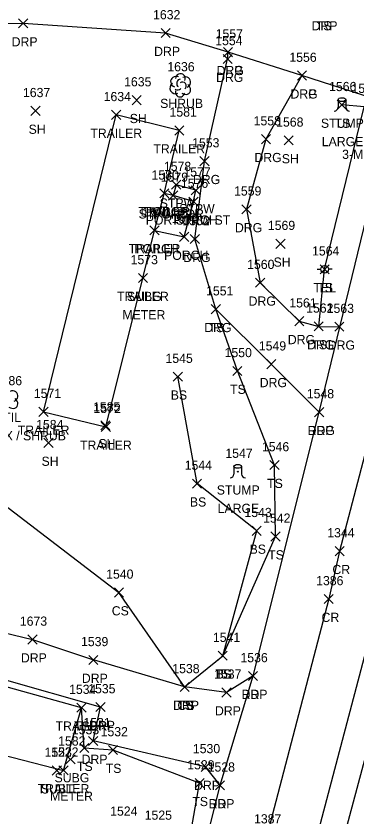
# Model space of a CAD drawing. Extents: x 1477930 to 1480780, y 774090 to 784647.
# Drawn here: x 1479279.7 to 1479353.8, y 774335.2 to 774509.5 of the extents above; entities that cross this region are included whole.
import ezdxf

# ---------------------------------------------------------------- set-up
doc = ezdxf.new("R2010")
doc.units = 0
for name, color, linetype in [('L_A', 7, 'Continuous'), ('L_C', 7, 'Continuous'), ('L_I', 7, 'Continuous'), ('L_TIC', 7, 'Continuous'), ('LBC', 7, 'Continuous'), ('LBF', 7, 'Continuous'), ('LELB', 7, 'Continuous'), ('LSH', 7, 'Continuous'), ('LTD', 7, 'Continuous'), ('LTS', 7, 'Continuous'), ('P_A', 7, 'Continuous'), ('P_I', 7, 'Continuous'), ('P_TIC', 7, 'Continuous'), ('PET', 7, 'Continuous'), ('PRC', 7, 'Continuous'), ('R_A', 7, 'Continuous'), ('R_I', 7, 'Continuous'), ('R_TIC', 7, 'Continuous'), ('RDG', 7, 'Continuous'), ('RDP', 7, 'Continuous'), ('RSW', 7, 'Continuous'), ('U_A', 7, 'Continuous'), ('U_C', 7, 'Continuous'), ('U_I', 7, 'Continuous'), ('U_TIC', 7, 'Continuous'), ('UP', 7, 'Continuous')]:
    doc.layers.add(name, color=color, linetype=linetype)

msp = doc.modelspace()

# ---------------------------------------------------------------- linework, layer by layer
at = {"layer": 'L_TIC'}
for points in [[(1479304.99, 774490.19), (1479306.99, 774492.19)], [(1479306.99, 774490.19), (1479304.99, 774492.19)], [(1479282.93, 774487.85), (1479284.93, 774489.85)], [(1479284.93, 774487.85), (1479282.93, 774489.85)], [(1479349.75, 774489.16), (1479351.75, 774491.16)], [(1479351.75, 774489.16), (1479349.75, 774491.16)], [(1479300.53, 774486.97), (1479302.53, 774488.97)], [(1479302.53, 774486.97), (1479300.53, 774488.97)], [(1479300.53, 774486.97), (1479302.53, 774488.97)], [(1479302.53, 774486.97), (1479300.53, 774488.97)], [(1479314.29, 774483.59), (1479316.29, 774485.59)], [(1479316.29, 774483.59), (1479314.29, 774485.59)], [(1479338.16, 774481.42), (1479340.16, 774483.42)], [(1479340.16, 774481.42), (1479338.16, 774483.42)], [(1479313.62, 774471.76), (1479315.62, 774473.76)], [(1479315.62, 774471.76), (1479313.62, 774473.76)], [(1479317.89, 774470.55), (1479319.89, 774472.55)], [(1479319.89, 774470.55), (1479317.89, 774472.55)], [(1479311.01, 774469.88), (1479313.01, 774471.88)], [(1479313.01, 774469.88), (1479311.01, 774471.88)], [(1479311.01, 774469.88), (1479313.01, 774471.88)], [(1479313.01, 774469.88), (1479311.01, 774471.88)], [(1479312.95, 774469.4), (1479314.95, 774471.4)], [(1479314.95, 774469.4), (1479312.95, 774471.4)], [(1479312.95, 774469.4), (1479314.95, 774471.4)], [(1479314.95, 774469.4), (1479312.95, 774471.4)], [(1479317.39, 774468.08), (1479319.39, 774470.08)], [(1479319.39, 774468.08), (1479317.39, 774470.08)], [(1479317.39, 774468.08), (1479319.39, 774470.08)], [(1479319.39, 774468.08), (1479317.39, 774470.08)], [(1479308.89, 774461.82), (1479310.89, 774463.82)], [(1479310.89, 774461.82), (1479308.89, 774463.82)], [(1479308.89, 774461.82), (1479310.89, 774463.82)], [(1479310.89, 774461.82), (1479308.89, 774463.82)], [(1479315.34, 774460.39), (1479317.34, 774462.39)], [(1479317.34, 774460.39), (1479315.34, 774462.39)], [(1479336.36, 774458.9), (1479338.36, 774460.9)], [(1479338.36, 774458.9), (1479336.36, 774460.9)], [(1479345.99, 774453.34), (1479347.99, 774455.34)], [(1479347.99, 774453.34), (1479345.99, 774455.34)], [(1479306.36, 774451.43), (1479308.36, 774453.43)], [(1479308.36, 774451.43), (1479306.36, 774453.43)], [(1479322.25, 774444.64), (1479324.25, 774446.64)], [(1479324.25, 774444.64), (1479322.25, 774446.64)], [(1479344.69, 774440.89), (1479346.69, 774442.89)], [(1479346.69, 774440.89), (1479344.69, 774442.89)], [(1479326.95, 774431.19), (1479328.95, 774433.19)], [(1479328.95, 774431.19), (1479326.95, 774433.19)], [(1479313.97, 774429.94), (1479315.97, 774431.94)], [(1479315.97, 774429.94), (1479313.97, 774431.94)], [(1479284.68, 774422.29), (1479286.68, 774424.29)], [(1479286.68, 774422.29), (1479284.68, 774424.29)], [(1479284.68, 774422.29), (1479286.68, 774424.29)], [(1479286.68, 774422.29), (1479284.68, 774424.29)], [(1479298.17, 774419.35), (1479300.17, 774421.35)], [(1479300.17, 774419.35), (1479298.17, 774421.35)], [(1479298.27, 774419.01), (1479300.27, 774421.01)], [(1479300.27, 774419.01), (1479298.27, 774421.01)], [(1479285.75, 774415.51), (1479287.75, 774417.51)], [(1479287.75, 774415.51), (1479285.75, 774417.51)], [(1479335.05, 774410.68), (1479337.05, 774412.68)], [(1479337.05, 774410.68), (1479335.05, 774412.68)], [(1479318.16, 774406.64), (1479320.16, 774408.64)], [(1479320.16, 774406.64), (1479318.16, 774408.64)], [(1479331.18, 774396.35), (1479333.18, 774398.35)], [(1479333.18, 774396.35), (1479331.18, 774398.35)], [(1479335.27, 774395.12), (1479337.27, 774397.12)], [(1479337.27, 774395.12), (1479335.27, 774397.12)], [(1479301.12, 774382.92), (1479303.12, 774384.92)], [(1479303.12, 774382.92), (1479301.12, 774384.92)], [(1479323.75, 774369.14), (1479325.75, 774371.14)], [(1479325.75, 774369.14), (1479323.75, 774371.14)], [(1479323.75, 774369.14), (1479325.75, 774371.14)], [(1479325.75, 774369.14), (1479323.75, 774371.14)], [(1479315.45, 774362.33), (1479317.45, 774364.33)], [(1479317.45, 774362.33), (1479315.45, 774364.33)], [(1479315.45, 774362.33), (1479317.45, 774364.33)], [(1479317.45, 774362.33), (1479315.45, 774364.33)], [(1479292.95, 774357.81), (1479294.95, 774359.81)], [(1479294.95, 774357.81), (1479292.95, 774359.81)], [(1479292.95, 774357.81), (1479294.95, 774359.81)], [(1479294.95, 774357.81), (1479292.95, 774359.81)], [(1479293.56, 774349.02), (1479295.56, 774351.02)], [(1479295.56, 774349.02), (1479293.56, 774351.02)], [(1479299.83, 774348.59), (1479301.83, 774350.59)], [(1479301.83, 774348.59), (1479299.83, 774350.59)], [(1479289.03, 774344.16), (1479291.03, 774346.16)], [(1479291.03, 774344.16), (1479289.03, 774346.16)], [(1479318.72, 774341.37), (1479320.72, 774343.37)], [(1479320.72, 774341.37), (1479318.72, 774343.37)]]:
    msp.add_lwpolyline(points, dxfattribs=at)
at = {"layer": 'LBC'}
for points in [[(1479285.68, 774423.29), (1479299.27, 774420.01), (1479307.36, 774452.43), (1479309.89, 774462.82), (1479312.01, 774470.88), (1479315.29, 774484.59), (1479301.53, 774487.97)], [(1479285.68, 774423.29), (1479301.53, 774487.97)], [(1479220.31, 774364.01), (1479269.03, 774350.77), (1479272.25, 774349.73), (1479290.03, 774345.16), (1479293.95, 774358.81), (1479249.22, 774371.2), (1479239.25, 774373.93), (1479224.24, 774377.86)]]:
    msp.add_lwpolyline(points, dxfattribs=at)
at = {"layer": 'LBF'}
for points in [[(1479318.39, 774469.08), (1479318.89, 774471.55), (1479314.62, 774472.76), (1479313.95, 774470.4)], [(1479309.89, 774462.82), (1479316.34, 774461.39), (1479318.39, 774469.08), (1479313.95, 774470.4), (1479312.01, 774470.88)]]:
    msp.add_lwpolyline(points, dxfattribs=at)
at = {"layer": 'LELB'}
for points in [[(1479345.69, 774441.89), (1479346.99, 774454.34), (1479355.59, 774489.75), (1479350.75, 774490.16)], [(1479316.45, 774363.33), (1479324.75, 774370.14), (1479336.27, 774396.12), (1479336.05, 774411.68), (1479327.95, 774432.19), (1479323.25, 774445.64)], [(1479324.75, 774370.14), (1479332.18, 774397.35), (1479319.16, 774407.64), (1479314.97, 774430.94)], [(1479269.11, 774409.12), (1479302.12, 774383.92)], [(1479316.45, 774363.33), (1479302.12, 774383.92)], [(1479286.59, 774212.27), (1479303.75, 774279.72), (1479306.97, 774294.46), (1479314.06, 774320.63), (1479317.48, 774329.95), (1479319.72, 774342.37), (1479300.83, 774349.59), (1479294.56, 774350.02), (1479293.95, 774358.81)]]:
    msp.add_lwpolyline(points, dxfattribs=at)
at = {"layer": 'LSH'}
msp.add_line((1479315.48, 774494.48), (1479315.48, 774494.48), dxfattribs=at)
msp.add_line((1479315.48, 774494.48), (1479315.48, 774494.48), dxfattribs=at)
msp.add_arc((1479315.53, 774495.91), 1.05, 335.5272, 180.9563, dxfattribs=at)
for centre, major_axis, ratio, start_param, end_param in [((1479314.69, 774495.15), (1.21, -0.51), 0.895232, 1.570796, 4.712389), ((1479315.27, 774494.94), (-0.208, -0.792), 0.645439, 3.141593, 6.283185), ((1479315.98, 774494.31), (-0.5, 0.667), 0.989748, 3.141593, 6.283185), ((1479316.52, 774495.06), (-1.14, -0.48), 0.949671, 1.570796, 4.712389), ((1479314.4, 774493.77), (0.58, -1.04), 0.959034, 3.141593, 6.283185), ((1479315.48, 774492.98), (0.26, 1.06), 0.942809, 1.570796, 4.712389), ((1479315.02, 774493.73), (-0.625, -0.083), 0.423636, 0, 3.141593), ((1479316.48, 774493.65), (-1.09, 0.79), 0.841452, 1.570796, 4.712389)]:
    msp.add_ellipse(centre, major_axis=major_axis, ratio=ratio, start_param=start_param, end_param=end_param, dxfattribs=at)
at = {"layer": 'LTD'}
for centre, major_axis, ratio in [((1479278.84, 774426.65), (-1.14, -0.48), 0.949671), ((1479278.8, 774425.23), (-1.09, 0.79), 0.841452)]:
    msp.add_ellipse(centre, major_axis=major_axis, ratio=ratio, start_param=1.570796, end_param=4.712389, dxfattribs=at)
at = {"layer": 'LTS'}
for p, q in [((1479349.92, 774491.3), (1479349.92, 774489.64)), ((1479350.76, 774490.16), (1479350.76, 774490.16)), ((1479350.76, 774490.16), (1479350.76, 774490.16)), ((1479350.76, 774490.14), (1479350.76, 774490.14)), ((1479351.59, 774491.14), (1479351.59, 774491.3)), ((1479351.59, 774491.3), (1479351.59, 774489.64)), ((1479327.21, 774411.39), (1479327.21, 774409.73)), ((1479328.87, 774411.23), (1479328.87, 774411.39)), ((1479328.87, 774411.39), (1479328.87, 774409.73)), ((1479328.04, 774410.25), (1479328.04, 774410.25)), ((1479328.04, 774410.25), (1479328.04, 774410.25)), ((1479328.04, 774410.23), (1479328.04, 774410.23))]:
    msp.add_line(p, q, dxfattribs=at)
for centre in [(1479350.76, 774490.16), (1479328.04, 774410.25)]:
    msp.add_circle(centre, 0.0833, dxfattribs=at)
for centre, start, end in [((1479349.09, 774489.64), 270, 360), ((1479352.42, 774489.64), 180, 270), ((1479326.37, 774409.73), 270, 360), ((1479329.71, 774409.73), 180, 270)]:
    msp.add_arc(centre, 0.833, start, end, dxfattribs=at)
for centre in [(1479350.76, 774491.3), (1479328.04, 774411.39)]:
    msp.add_ellipse(centre, major_axis=(-0.833, 0), ratio=0.5, dxfattribs=at)
at = {"layer": 'P_TIC'}
for points in [[(1479344.79, 774422.22), (1479346.79, 774424.22)], [(1479346.79, 774422.22), (1479344.79, 774424.22)], [(1479349.26, 774391.93), (1479351.26, 774393.93)], [(1479351.26, 774391.93), (1479349.26, 774393.93)], [(1479346.88, 774381.5), (1479348.88, 774383.5)], [(1479348.88, 774381.5), (1479346.88, 774383.5)], [(1479330.38, 774364.72), (1479332.38, 774366.72)], [(1479332.38, 774364.72), (1479330.38, 774366.72)], [(1479323.18, 774340.9), (1479325.18, 774342.9)], [(1479325.18, 774340.9), (1479323.18, 774342.9)]]:
    msp.add_lwpolyline(points, dxfattribs=at)
at = {"layer": 'PET'}
for points in [[(1479290.45, 774211), (1479306.91, 774277.39), (1479311.78, 774295.77), (1479318.73, 774320.25), (1479320.95, 774328.78), (1479324.18, 774341.9), (1479331.38, 774365.72), (1479345.79, 774423.22), (1479362.09, 774490.12), (1479368.03, 774516.32), (1479374.9, 774550.83), (1479383.52, 774593.51), (1479391.98, 774640.39), (1479380.39, 774660.29), (1479367.57, 774658.29), (1479344.84, 774648.04), (1479309.03, 774631.85), (1479275.88, 774616.72), (1479247.66, 774604.4), (1479226.65, 774595.78), (1479182.4, 774576.78), (1479137.48, 774556.65)], [(1479393.7, 774517.71), (1479389.34, 774499.77), (1479385.65, 774485.2), (1479372.47, 774434.64), (1479369.27, 774419.38), (1479364.55, 774403.36), (1479358.32, 774380), (1479344.31, 774327.21), (1479344.11, 774325.21), (1479340.22, 774308.9), (1479335.03, 774292.91), (1479323.53, 774246.41), (1479312.91, 774202.88), (1479309.56, 774191.22), (1479295.39, 774137.13)]]:
    msp.add_lwpolyline(points, dxfattribs=at)
at = {"layer": 'PRC'}
msp.add_lwpolyline([(1479418.32, 774694.97), (1479413.6, 774667.54), (1479403.41, 774616.88), (1479393.18, 774569.31), (1479382.15, 774520.62), (1479370.95, 774473.44), (1479362, 774437.8), (1479350.26, 774392.93), (1479347.88, 774382.5), (1479334.29, 774330.6), (1479333.84, 774328.63), (1479325.02, 774295.54), (1479313.51, 774250.57), (1479296.99, 774187.82), (1479284.93, 774140.68)], dxfattribs=at)
at = {"layer": 'R_TIC'}
for points in [[(1479280.23, 774506.91), (1479282.23, 774508.91)], [(1479282.23, 774506.91), (1479280.23, 774508.91)], [(1479311.31, 774504.81), (1479313.31, 774506.81)], [(1479313.31, 774504.81), (1479311.31, 774506.81)], [(1479324.92, 774500.65), (1479326.92, 774502.65)], [(1479326.92, 774500.65), (1479324.92, 774502.65)], [(1479324.92, 774500.65), (1479326.92, 774502.65)], [(1479326.92, 774500.65), (1479324.92, 774502.65)], [(1479324.83, 774499.16), (1479326.83, 774501.16)], [(1479326.83, 774499.16), (1479324.83, 774501.16)], [(1479341.05, 774495.54), (1479343.05, 774497.54)], [(1479343.05, 774495.54), (1479341.05, 774497.54)], [(1479341.05, 774495.54), (1479343.05, 774497.54)], [(1479343.05, 774495.54), (1479341.05, 774497.54)], [(1479333.19, 774481.69), (1479335.19, 774483.69)], [(1479335.19, 774481.69), (1479333.19, 774483.69)], [(1479319.78, 774476.9), (1479321.78, 774478.9)], [(1479321.78, 774476.9), (1479319.78, 774478.9)], [(1479328.94, 774466.4), (1479330.94, 774468.4)], [(1479330.94, 774466.4), (1479328.94, 774468.4)], [(1479317.68, 774459.92), (1479319.68, 774461.92)], [(1479319.68, 774459.92), (1479317.68, 774461.92)], [(1479331.92, 774450.41), (1479333.92, 774452.41)], [(1479333.92, 774450.41), (1479331.92, 774452.41)], [(1479322.25, 774444.64), (1479324.25, 774446.64)], [(1479324.25, 774444.64), (1479322.25, 774446.64)], [(1479340.47, 774442.02), (1479342.47, 774444.02)], [(1479342.47, 774442.02), (1479340.47, 774444.02)], [(1479344.69, 774440.89), (1479346.69, 774442.89)], [(1479346.69, 774440.89), (1479344.69, 774442.89)], [(1479349.18, 774440.82), (1479351.18, 774442.82)], [(1479351.18, 774440.82), (1479349.18, 774442.82)], [(1479334.35, 774432.65), (1479336.35, 774434.65)], [(1479336.35, 774432.65), (1479334.35, 774434.65)], [(1479344.79, 774422.22), (1479346.79, 774424.22)], [(1479346.79, 774422.22), (1479344.79, 774424.22)], [(1479282.25, 774372.67), (1479284.25, 774374.67)], [(1479284.25, 774372.67), (1479282.25, 774374.67)], [(1479295.55, 774368.22), (1479297.55, 774370.22)], [(1479297.55, 774368.22), (1479295.55, 774370.22)], [(1479330.38, 774364.72), (1479332.38, 774366.72)], [(1479332.38, 774364.72), (1479330.38, 774366.72)], [(1479315.45, 774362.33), (1479317.45, 774364.33)], [(1479317.45, 774362.33), (1479315.45, 774364.33)], [(1479324.58, 774361.14), (1479326.58, 774363.14)], [(1479326.58, 774361.14), (1479324.58, 774363.14)], [(1479297.11, 774357.95), (1479299.11, 774359.95)], [(1479299.11, 774357.95), (1479297.11, 774359.95)], [(1479295.49, 774350.57), (1479297.49, 774352.57)], [(1479297.49, 774350.57), (1479295.49, 774352.57)], [(1479320.03, 774344.9), (1479322.03, 774346.9)], [(1479322.03, 774344.9), (1479320.03, 774346.9)], [(1479323.18, 774340.9), (1479325.18, 774342.9)], [(1479325.18, 774340.9), (1479323.18, 774342.9)]]:
    msp.add_lwpolyline(points, dxfattribs=at)
at = {"layer": 'RDG'}
for points in [[(1479345.79, 774423.22), (1479335.35, 774433.65), (1479323.25, 774445.64), (1479318.68, 774460.92), (1479320.78, 774477.9), (1479325.83, 774500.16), (1479325.92, 774501.65)], [(1479342.05, 774496.54), (1479334.19, 774482.69), (1479329.94, 774467.4), (1479332.92, 774451.41), (1479341.47, 774443.02), (1479345.69, 774441.89), (1479350.18, 774441.82)]]:
    msp.add_lwpolyline(points, dxfattribs=at)
at = {"layer": 'RDP'}
for points in [[(1479362.09, 774490.12), (1479342.05, 774496.54), (1479325.92, 774501.65), (1479312.31, 774505.81), (1479281.23, 774507.91), (1479260.19, 774507.51), (1479228.52, 774504.28), (1479173.38, 774482.97), (1479136.11, 774464.13), (1479110.89, 774453.25), (1479073.73, 774438.02), (1479028.37, 774422.34), (1479014.07, 774419.45), (1479003.41, 774415.12), (1479000.29, 774404.19), (1478987.91, 774394.73), (1478976.96, 774410.39), (1478964.4, 774425.19), (1478951.82, 774441.87), (1478940.93, 774454.02), (1478935.82, 774456.7)], [(1479256.83, 774377.19), (1479257.63, 774379.86), (1479283.25, 774373.67)], [(1479283.25, 774373.67), (1479296.55, 774369.22)], [(1479324.18, 774341.9), (1479321.03, 774345.9), (1479296.49, 774351.57), (1479298.11, 774358.95), (1479255.13, 774371.1)], [(1479331.38, 774365.72), (1479325.58, 774362.14), (1479316.45, 774363.33), (1479296.55, 774369.22)]]:
    msp.add_lwpolyline(points, dxfattribs=at)
at = {"layer": 'RSW'}
msp.add_lwpolyline([(1479439.59, 774678.84), (1479428.06, 774631.68), (1479427.69, 774629.39), (1479423.62, 774612.61), (1479412.13, 774564.62), (1479400.05, 774515.9), (1479395.35, 774496.7), (1479392.07, 774484.83), (1479378.7, 774433.47), (1479373.97, 774416.64), (1479370.99, 774405.04), (1479364.01, 774378.3), (1479349.72, 774325.26), (1479349.32, 774323.81), (1479344.48, 774305.55), (1479341.14, 774293.48), (1479328.32, 774245.21), (1479314.62, 774191.4)], dxfattribs=at)
at = {"layer": 'U_TIC'}
for points in [[(1479306.36, 774451.43), (1479308.36, 774453.43)], [(1479308.36, 774451.43), (1479306.36, 774453.43)], [(1479290.56, 774346.55), (1479292.56, 774348.55)], [(1479292.56, 774346.55), (1479290.56, 774348.55)], [(1479287.59, 774344.12), (1479289.59, 774346.12)], [(1479289.59, 774344.12), (1479287.59, 774346.12)]]:
    msp.add_lwpolyline(points, dxfattribs=at)
at = {"layer": 'UP'}
for p, q in [((1479345.34, 774454.33), (1479346.16, 774454.33)), ((1479346.99, 774454.34), (1479346.99, 774454.34)), ((1479348.66, 774454.34), (1479347.83, 774454.34)), ((1479347.83, 774454.34), (1479347.83, 774454.34)), ((1479348.66, 774454.34), (1479348.66, 774454.34))]:
    msp.add_line(p, q, dxfattribs=at)
msp.add_circle((1479346.99, 774454.34), 0.833, dxfattribs=at)

# ---------------------------------------------------------------- texts
at = {"layer": 'L_A'}
for s, p in [('TS', (1479345.07, 774506.39)), ('SHRUB', (1479311.11, 774489.48)), ('SH', (1479304.48, 774486.19)), ('STUMP', (1479346.18, 774485.16)), ('TS', (1479349.16, 774485.16)), ('SH', (1479282.42, 774483.85)), ('TRAILER', (1479295.89, 774482.97)), ('TRAILER', (1479295.89, 774482.97)), ('TRAILER', (1479309.64, 774479.59)), ('SH', (1479337.65, 774477.42)), ('STPW', (1479311.02, 774467.76)), ('TRAILER', (1479306.36, 774465.88)), ('STPW POR', (1479306.4, 774465.4)), ('PORCH', (1479307.63, 774465.88)), ('PORCH', (1479309.58, 774465.4)), ('STPW', (1479315.28, 774466.55)), ('POR STPW ST', (1479307.97, 774464.08)), ('PORCH', (1479314.01, 774464.08)), ('TRAILER', (1479304.24, 774457.82)), ('PORCH', (1479305.51, 774457.82)), ('PORCH', (1479311.97, 774456.39)), ('SH', (1479335.85, 774454.9)), ('TS', (1479345.4, 774449.34)), ('TRAILER', (1479301.71, 774447.43)), ('TS', (1479321.66, 774440.64)), ('TS', (1479344.1, 774436.89)), ('TS', (1479326.36, 774427.19)), ('BS', (1479313.42, 774425.94)), ('TRAILER', (1479280.04, 774418.29)), ('TRAILER', (1479280.04, 774418.29)), ('TRAILER', (1479293.63, 774415.01)), ('SH', (1479297.65, 774415.35)), ('SH', (1479285.24, 774411.51)), ('TS', (1479334.46, 774406.68)), ('STUMP', (1479323.46, 774405.25)), ('BS', (1479317.6, 774402.64)), ('BS', (1479330.62, 774392.35)), ('TS', (1479334.68, 774391.12)), ('CS', (1479300.56, 774378.92)), ('TS', (1479323.16, 774365.14)), ('BS', (1479323.19, 774365.14)), ('TS', (1479314.86, 774358.33)), ('CS', (1479314.89, 774358.33)), ('TRAILER', (1479288.3, 774353.81)), ('TS', (1479292.36, 774353.81)), ('TS', (1479292.97, 774345.02)), ('TS', (1479299.24, 774344.59)), ('TRAILER', (1479284.38, 774340.16)), ('TS', (1479318.13, 774337.37))]:
    msp.add_text(s, height=2, dxfattribs=at).set_placement(p)
at = {"layer": 'L_C'}
for s, p in [('LARGE', (1479346.37, 774481.16)), ('3-MB 13/5', (1479350.81, 774478.38)), ('METER', (1479302.89, 774443.43)), ('LARGE', (1479323.66, 774401.25))]:
    msp.add_text(s, height=2, dxfattribs=at).set_placement(p)
at = {"layer": 'L_I'}
for s, p in [('1636', (1479312.68, 774497.48)), ('1635', (1479303.25, 774494.19)), ('1566', (1479347.96, 774493.16)), ('1566', (1479347.96, 774493.16)), ('1637', (1479281.19, 774491.85)), ('1565', (1479352.85, 774492.75)), ('1634', (1479298.79, 774490.97)), ('1634', (1479298.79, 774490.97)), ('1581', (1479313.16, 774487.59)), ('1568', (1479336.42, 774485.42)), ('1578', (1479311.93, 774475.76)), ('1580', (1479309.23, 774473.88)), ('1580', (1479309.23, 774473.88)), ('1577', (1479316.19, 774474.55)), ('1579', (1479311.25, 774473.4)), ('1579', (1479311.25, 774473.4)), ('1576', (1479315.64, 774472.08)), ('1576', (1479315.64, 774472.08)), ('1574', (1479307.19, 774465.82)), ('1574', (1479307.19, 774465.82)), ('1575', (1479313.65, 774464.39)), ('1569', (1479334.61, 774462.9)), ('1564', (1479344.25, 774457.34)), ('1573', (1479304.67, 774455.43)), ('1551', (1479321.13, 774448.64)), ('1562', (1479342.95, 774444.89)), ('1545', (1479312.28, 774433.94)), ('1550', (1479325.17, 774435.19)), ('1586', (1479275.05, 774429.07)), ('1571', (1479283.56, 774426.29)), ('1571', (1479283.56, 774426.29)), ('1585', (1479296.47, 774423.35)), ('1572', (1479296.58, 774423.01)), ('1584', (1479284.06, 774419.51)), ('1546', (1479333.31, 774414.68)), ('1547', (1479325.34, 774413.25)), ('1544', (1479316.46, 774410.64)), ('1543', (1479329.49, 774400.35)), ('1542', (1479333.58, 774399.12)), ('1540', (1479299.34, 774386.92)), ('1541', (1479322.62, 774373.14)), ('1541', (1479322.62, 774373.14)), ('1538', (1479313.76, 774366.33)), ('1538', (1479313.76, 774366.33)), ('1534', (1479291.25, 774361.81)), ('1534', (1479291.25, 774361.81)), ('1533', (1479291.86, 774353.02)), ('1532', (1479298.13, 774352.59)), ('1522', (1479287.34, 774348.16)), ('1529', (1479317.02, 774345.37)), ('1524', (1479300.21, 774335.28)), ('1525', (1479307.74, 774334.4))]:
    msp.add_text(s, height=2, dxfattribs=at).set_placement(p)
at = {"layer": 'P_A'}
for s, p in [('RDP', (1479343.28, 774418.22)), ('CR', (1479348.7, 774387.93)), ('CR', (1479346.32, 774377.5)), ('RDP', (1479328.87, 774360.72)), ('RDP', (1479321.66, 774336.9))]:
    msp.add_text(s, height=2, dxfattribs=at).set_placement(p)
at = {"layer": 'P_I'}
for s, p in [('1548', (1479343.1, 774426.22)), ('1344', (1479347.57, 774395.93)), ('1386', (1479345.14, 774385.5)), ('1536', (1479328.63, 774368.72)), ('1528', (1479321.48, 774344.9)), ('1387', (1479331.59, 774333.6))]:
    msp.add_text(s, height=2, dxfattribs=at).set_placement(p)
at = {"layer": 'R_A'}
for s, p in [('DRP', (1479344.15, 774506.39)), ('DRP', (1479278.72, 774502.91)), ('DRP', (1479309.8, 774500.81)), ('DRG', (1479323.41, 774496.65)), ('DRP', (1479323.41, 774496.65)), ('DRG', (1479323.32, 774495.16)), ('DRG', (1479339.54, 774491.54)), ('DRP', (1479339.54, 774491.54)), ('DRG', (1479331.68, 774477.69)), ('DRG', (1479318.27, 774472.9)), ('DRG', (1479327.43, 774462.4)), ('DRG', (1479316.17, 774455.92)), ('DRG', (1479330.41, 774446.41)), ('DRG', (1479320.74, 774440.64)), ('DRG', (1479338.96, 774438.02)), ('DRG', (1479343.17, 774436.89)), ('DRG', (1479347.67, 774436.82)), ('DRG', (1479332.83, 774428.65)), ('DRG', (1479343.28, 774418.22)), ('DRP', (1479280.74, 774368.67)), ('DRP', (1479294.04, 774364.22)), ('DRP', (1479328.87, 774360.72)), ('DRP', (1479313.94, 774358.33)), ('DRP', (1479323.07, 774357.14)), ('DRP', (1479295.6, 774353.95)), ('DRP', (1479293.98, 774346.57)), ('DRP', (1479318.52, 774340.9)), ('DRP', (1479321.66, 774336.9))]:
    msp.add_text(s, height=2, dxfattribs=at).set_placement(p)
at = {"layer": 'R_I'}
for s, p in [('1632', (1479309.57, 774508.81)), ('1557', (1479323.23, 774504.65)), ('1557', (1479323.23, 774504.65)), ('1554', (1479323.13, 774503.16)), ('1556', (1479339.3, 774499.54)), ('1556', (1479339.3, 774499.54)), ('1558', (1479331.5, 774485.69)), ('1553', (1479318.09, 774480.9)), ('1559', (1479327.24, 774470.4)), ('1552', (1479315.98, 774463.92)), ('1560', (1479330.09, 774454.41)), ('1551', (1479321.13, 774448.64)), ('1561', (1479339.29, 774446.02)), ('1562', (1479342.95, 774444.89)), ('1563', (1479347.44, 774444.82)), ('1549', (1479332.64, 774436.65)), ('1548', (1479343.1, 774426.22)), ('1673', (1479280.51, 774376.67)), ('1539', (1479293.85, 774372.22)), ('1536', (1479328.63, 774368.72)), ('1538', (1479313.76, 774366.33)), ('1537', (1479322.89, 774365.14)), ('1535', (1479295.42, 774361.95)), ('1531', (1479294.37, 774354.57)), ('1530', (1479318.25, 774348.9)), ('1528', (1479321.48, 774344.9))]:
    msp.add_text(s, height=2, dxfattribs=at).set_placement(p)
at = {"layer": 'U_A'}
for s, p in [('TEL', (1479344.55, 774449.34)), ('SUBG', (1479303.89, 774447.43)), ('UTIL', (1479274.96, 774421.07)), ('SUBG', (1479288.08, 774342.55)), ('SUBT', (1479285.09, 774340.12))]:
    msp.add_text(s, height=2, dxfattribs=at).set_placement(p)
at = {"layer": 'U_C'}
for s, p in [('EL METER BOX / SHRUB', (1479259.21, 774417.07)), ('METER', (1479287.09, 774338.55))]:
    msp.add_text(s, height=2, dxfattribs=at).set_placement(p)
at = {"layer": 'U_I'}
for s, p in [('1564', (1479344.25, 774457.34)), ('1573', (1479304.67, 774455.43)), ('1586', (1479275.05, 774429.07)), ('1582', (1479288.86, 774350.55)), ('1523', (1479285.9, 774348.12))]:
    msp.add_text(s, height=2, dxfattribs=at).set_placement(p)

doc.saveas('drawing.dxf')
